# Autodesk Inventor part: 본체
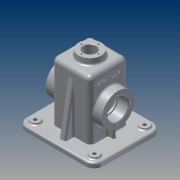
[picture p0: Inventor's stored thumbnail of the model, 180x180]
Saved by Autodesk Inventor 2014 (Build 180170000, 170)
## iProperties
Created: 2015-12
Part Number: 본체
Material: 알루미늄 6061
Document SubType Name: Modeling
Designer: Administrator
Density: 2.71 g/cm^3
Appearance: 알루미늄 - 평지
Mass: 801.49 g
Surface Area: 918.504 cm^2
Volume: 295.753 cm^3
Author: Administrator
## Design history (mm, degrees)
sketch "스케치1"
  geometry: L1 (-50, 57.5)-(50, 57.5); L2 (65, 42.5)-(65, -42.5); L3 (50, -57.5)-(-50, -57.5); L4 (-65, -42.5)-(-65, 42.5); A1 r 15 centre (-50, 42.5) between (-50, 57.5) and (-65, 42.5); A2 r 15 centre (50, 42.5) between (65, 42.5) and (50, 57.5); A3 r 15 centre (50, -42.5) between (50, -57.5) and (65, -42.5); A4 r 15 centre (-50, -42.5) between (-65, -42.5) and (-50, -57.5); 6 further points
  constraints: 8 end point, 8 point on circle, 8 tangent, 6 point on line, 4 centre point, 3 equal radius, 2 midpoint, 2 parallel, 1 horizontal, 1 horizontal alignment, 1 perpendicular, 1 vertical alignment
  dimensions: "d0" = 130 distance of point (-65, 57.5) point (65, 57.5); "d1" = 115 distance of point (65, 57.5) point (65, -57.5); "d2" = 15 radius of A1
extrude "돌출1" new body sketch "스케치1" distance "d3" = 10; taper "d4" = 0 deg
sketch "스케치2"
  geometry: L1 (-32.5, 32.5)-(32.5, 32.5); L2 (32.5, 32.5)-(32.5, -32.5); L3 (32.5, -32.5)-(-32.5, -32.5); L4 (-32.5, -32.5)-(-32.5, 32.5); 3 further points
  constraints: 8 end point, 2 midpoint, 2 parallel, 1 horizontal, 1 horizontal alignment, 1 perpendicular, 1 vertical alignment
  dimensions: "d5" = 65 distance of L1.end L2.end; "d6" = 65 distance of L1.start L1.end
extrude "돌출2" join sketch "스케치2" distance "d7" = 100; taper "d8" = 0 deg
sketch "스케치6"
  geometry: C1 r 27.5 at (-45, 32.5); 1 further point
  constraints: 1 centre point
  dimensions: "d17" = 55 distance of point (10, 32.5) C1.centre; "d18" = 55 diameter of C1
extrude "돌출3" join sketch "스케치6" distance "d19" = 15; taper "d20" = 0 deg
hole "구멍1" diameter "d23" = 30; stored, may be unused: countersink angle "d27" = 90 deg, drill point angle "d29" = 118 deg; dims "d24" = 6, "d25" = 35, "d26" = 17, "d28" = 8, "d30" = 10, "d31" = 10
sketch "스케치7"
  geometry: C1 r 17.5 at (0, 0) reference; 2 further points
  constraints: 1 horizontal alignment
  dimensions: "d32" = 21 distance of C1.centre point (-21, 0)
hole "구멍2" sketch "스케치7" at (-21, 0) diameter "d33" = 3.242; stored, may be unused: countersink angle "d37" = 90 deg, drill point angle "d39" = 118 deg; dims "d34" = 8, "d35" = 42, "d36" = 17, "d38" = 10
sketch "스케치8"
  geometry: L1 (-27.5, 27.5)-(27.5, 27.5); L2 (27.5, 27.5)-(27.5, -27.5); L3 (27.5, -27.5)-(-27.5, -27.5); L4 (-27.5, -27.5)-(-27.5, 27.5); 3 further points
  constraints: 8 end point, 2 midpoint, 2 parallel, 1 horizontal, 1 horizontal alignment, 1 perpendicular, 1 vertical alignment
  dimensions: "d43" = 55 distance of L1.start L1.end; "d44" = 55 distance of L1.end L2.end
extrude "돌출4" cut sketch "스케치8" distance "d45" = 105; taper "d46" = 0 deg
sketch "스케치9"
  geometry: C1 r 20 at (0, 0); 1 further point
  constraints: 1 centre point, 1 coincident
  dimensions: "d47" = 40 diameter of C1
extrude "돌출5" join sketch "스케치9" distance "d48" = 10; taper "d49" = -5 deg
hole "구멍3" diameter "d52" = 21; stored, may be unused: countersink angle "d56" = 90 deg, drill point angle "d58" = 118 deg; dims "d50" = 10, "d51" = 10, "d53" = 8, "d54" = 42, "d55" = 17, "d57" = 10
sketch "스케치10"
  geometry: C1 r 10.5 at (0, 0) reference; 1 further point
  constraints: 1 horizontal alignment
  dimensions: "d59" = 14.5 distance of point (14.5, 0) C1.centre
hole "구멍4" sketch "스케치10" at (14.5, 0) diameter "d60" = 2.459; stored, may be unused: countersink angle "d64" = 90 deg, drill point angle "d66" = 118 deg; dims "d61" = 7, "d62" = 42, "d63" = 17, "d65" = 9
sketch "스케치11"
  geometry: L1 (50, 57.5)-(-50, 57.5) reference; L2 (-65, 42.5)-(-65, -42.5) reference; L3 (-50, -57.5)-(50, -57.5) reference; L4 (65, -42.5)-(65, 42.5) reference; L5 (-50, 52.5)-(50, 52.5); L6 (60, 42.5)-(60, -42.5); L7 (50, -52.5)-(-50, -52.5); L8 (-60, -42.5)-(-60, 42.5); A1 r 15 centre (-50, 42.5) between (-50, 57.5) and (-65, 42.5) reference; A2 r 15 centre (-50, -42.5) between (-65, -42.5) and (-50, -57.5) reference; A3 r 15 centre (50, -42.5) between (50, -57.5) and (65, -42.5) reference; A4 r 15 centre (50, 42.5) between (65, 42.5) and (50, 57.5) reference; A5 r 10 centre (-50, 42.5) between (-50, 52.5) and (-60, 42.5); A6 r 10 centre (50, 42.5) between (60, 42.5) and (50, 52.5); A7 r 10 centre (50, -42.5) between (50, -52.5) and (60, -42.5); A8 r 10 centre (-50, -42.5) between (-60, -42.5) and (-50, -52.5); 6 further points
  constraints: 8 end point, 8 point on circle, 8 tangent, 6 point on line, 4 centre point, 3 equal radius, 2 midpoint, 2 parallel, 1 horizontal, 1 horizontal alignment, 1 perpendicular, 1 vertical alignment
  dimensions: "d70" = 120 distance of point (-60, 52.5) point (60, 52.5); "d71" = 105 distance of point (60, 52.5) point (60, -52.5); "d72" = 10 radius of A5
extrude "돌출6" cut sketch "스케치11" distance "d73" = 2; taper "d74" = 0 deg
sketch "스케치12"
  geometry: C1 r 7.5 at (-50, 42.5); C2 r 7.5 at (-50, -42.5); C3 r 7.5 at (50, -42.5); C4 r 7.5 at (50, 42.5); A1 r 15 centre (-50, 42.5) between (-50, 57.5) and (-65, 42.5) reference; A2 r 15 centre (-50, -42.5) between (-65, -42.5) and (-50, -57.5) reference; A3 r 15 centre (50, -42.5) between (50, -57.5) and (65, -42.5) reference; A4 r 15 centre (50, 42.5) between (65, 42.5) and (50, 57.5) reference; 1 further point
  constraints: 4 centre point, 4 coincident, 2 equal radius
  dimensions: "d75" = 15 diameter of C1; "d76" = 15 diameter of C2
extrude "돌출7" join sketch "스케치12" distance "d77" = 3; taper "d78" = 0 deg
sketch "스케치13"
  geometry: C1 r 7.5 at (0, 0) reference; C2 r 7.5 at (0, 85) reference; C3 r 7.5 at (-100, 85) reference; C4 r 7.5 at (-100, 0) reference; 5 further points
  constraints: 4 coincident
hole "구멍5" sketch "스케치13" at (-100, 85), (-100, 0), (0, 0), (0, 85) diameter "d79" = 6; stored, may be unused: countersink angle "d83" = 90 deg, drill point angle "d85" = 118 deg; dims "d80" = 7, "d81" = 42, "d82" = 17, "d84" = 9
sketch "스케치14"
  geometry: L1 (32.5, 82.5)-(47.5, 82.5) reference; L2 (47.5, 82.5)-(47.5, 77.621) reference; L3 (47.5, 77.621)-(37.5, 77.621) reference; L4 (37.5, 77.621)-(36.526, 76) reference; L5 (36.526, 76)-(37.5, 74.379) reference; L6 (37.5, 74.379)-(47.5, 74.379) reference; L7 (47.5, 74.379)-(47.5, 72.5) reference; L8 (47.5, 72.5)-(30.5, 72.5) reference; L9 (30.5, 72.5)-(30.5, 70) reference; L10 (30.5, 70)-(27.5, 70) reference; L11 (27.5, 70)-(27.5, 105) reference; L12 (27.5, 105)-(10.5, 105) reference; L13 (10.5, 105)-(10.5, 120) reference; L14 (10.5, 120)-(13.271, 120) reference; L15 (13.271, 120)-(13.271, 111) reference; L16 (13.271, 111)-(14.5, 110.261) reference; L17 (14.5, 110.261)-(15.73, 111) reference; L18 (15.73, 111)-(15.73, 120) reference; L19 (15.73, 120)-(19.125, 120) reference; L20 (19.125, 120)-(20, 110) reference; L21 (20, 110)-(32.5, 110) reference; L22 (32.5, 110)-(32.5, 82.5) reference; L23 (47.5, 27.5)-(32.5, 27.5) reference; L24 (32.5, 27.5)-(32.5, 10) reference; L25 (32.5, 10)-(65, 10) reference; L26 (65, 10)-(65, 2) reference; L27 (65, 2)-(60, 2) reference; L28 (60, 2)-(60, 0) reference; L29 (60, 0)-(27.5, 0) reference; L30 (27.5, 0)-(27.5, 40) reference; L31 (27.5, 40)-(30.5, 40) reference; L32 (30.5, 40)-(30.5, 37.5) reference; L33 (30.5, 37.5)-(47.5, 37.5) reference; L34 (47.5, 37.5)-(47.5, 35.621) reference; L35 (47.5, 35.621)-(37.5, 35.621) reference; L36 (37.5, 35.621)-(36.526, 34) reference; L37 (36.526, 34)-(37.5, 32.379) reference; L38 (37.5, 32.379)-(47.5, 32.379) reference; L39 (47.5, 32.379)-(47.5, 27.5) reference; L40 (-47.5, 82.5)-(-32.5, 82.5) reference; L41 (-32.5, 82.5)-(-32.5, 110) reference; L42 (-32.5, 110)-(-20, 110) reference; L43 (-20, 110)-(-19.125, 120) reference; L44 (-19.125, 120)-(-15.73, 120) reference; L45 (-15.73, 120)-(-15.73, 111) reference; L46 (-15.73, 111)-(-14.5, 110.261) reference; L47 (-14.5, 110.261)-(-13.271, 111) reference; L48 (-13.271, 111)-(-13.271, 120) reference; L49 (-13.271, 120)-(-10.5, 120) reference; L50 (-10.5, 120)-(-10.5, 105) reference; L51 (-10.5, 105)-(-27.5, 105) reference; L52 (-27.5, 105)-(-27.5, 70) reference; L53 (-27.5, 70)-(-30.5, 70) reference; L54 (-30.5, 70)-(-30.5, 72.5) reference; L55 (-30.5, 72.5)-(-47.5, 72.5) reference; L56 (-47.5, 72.5)-(-47.5, 74.379) reference; L57 (-47.5, 74.379)-(-37.5, 74.379) reference; L58 (-37.5, 74.379)-(-36.526, 76) reference; L59 (-36.526, 76)-(-37.5, 77.621) reference; L60 (-37.5, 77.621)-(-47.5, 77.621) reference; L61 (-47.5, 77.621)-(-47.5, 82.5) reference; L62 (-32.5, 27.5)-(-47.5, 27.5) reference; L63 (-47.5, 27.5)-(-47.5, 32.379) reference; L64 (-47.5, 32.379)-(-37.5, 32.379) reference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; 1 further point
  constraints: 16 end point, 4 collinear, 2 point on line, 2 vertical, 1 parallel, 1 perpendicular
  dimensions: "d87" = 15 distance between parallel lines of L72 L79; "d88" = 15 distance between parallel lines of L80 L30; "d89" = 20.28589 distance of L79.start L79.end; "d90" = 20.28651 distance of L80.start L80.end
extrude "돌출8" join sketch "스케치14" stored distance "d91" = 6; taper "d92" = 0 deg
sketch "스케치15"
  geometry: L1 (-32.5, 10)-(-32.5, 110) reference; L2 (-32.5, 110)-(-20, 110) reference; L3 (-20, 110)-(-19.125, 120) reference; L4 (-19.125, 120)-(-15.73, 120) reference; L5 (-15.73, 120)-(-15.73, 111) reference; L6 (-15.73, 111)-(-14.5, 110.261) reference; L7 (-14.5, 110.261)-(-13.271, 111) reference; L8 (-13.271, 111)-(-13.271, 120) reference; L9 (-13.271, 120)-(-10.5, 120) reference; L10 (-10.5, 120)-(-10.5, 105) reference; L11 (-10.5, 105)-(-27.5, 105) reference; L12 (-27.5, 105)-(-27.5, 0) reference; L13 (-27.5, 0)-(-52.5, 0) reference; L14 (-52.5, 0)-(-52.5, 2) reference; L15 (-52.5, 2)-(-57.5, 2) reference; L16 (-57.5, 2)-(-57.5, 10) reference; L17 (-57.5, 10)-(-32.5, 10) reference; L18 (32.5, 110)-(32.5, 10) reference; L19 (32.5, 10)-(57.5, 10) reference; L20 (57.5, 10)-(57.5, 2) reference; L21 (57.5, 2)-(52.5, 2) reference; L22 (52.5, 2)-(52.5, 0) reference; L23 (52.5, 0)-(27.5, 0) reference; L24 (27.5, 0)-(27.5, 105) reference; L25 (27.5, 105)-(10.5, 105) reference; L26 (10.5, 105)-(10.5, 120) reference; L27 (10.5, 120)-(13.271, 120) reference; L28 (13.271, 120)-(13.271, 111) reference; L29 (13.271, 111)-(14.5, 110.261) reference; L30 (14.5, 110.261)-(15.73, 111) reference; L31 (15.73, 111)-(15.73, 120) reference; L32 (15.73, 120)-(19.125, 120) reference; L33 (19.125, 120)-(20, 110) reference; L34 (20, 110)-(32.5, 110) reference; L35 (-32.5, 95.069)-(-47.5, 10); L36 (32.5, 95.069)-(47.5, 10); 1 further point
  constraints: 4 end point, 4 point on line
  dimensions: "d93" = 10 deg angle of L35 L16; "d94" = 10 deg angle of L20 L36; "d95" = 10 distance from line of L35.end L16; "d96" = 10 distance from line of L36.end L20
extrude "돌출9" join sketch "스케치15" stored distance "d97" = 10; taper "d98" = 0 deg
chamfer "모따기1" distance "d99" = 1; stored, may be unused: second distance "d100" = 2, angle "d101" = 45 deg
fillet "모깎기2" dims "d102" = 0.3
fillet "모깎기3" dims "d103" = 8
fillet "모깎기4" dims "d104" = 3
fillet "모깎기5" dims "d105" = 3
fillet "모깎기6" dims "d106" = 3
fillet "모깎기7" dims "d107" = 1
sketch "스케치17"
  geometry: L1 (0, -8)-(91, -8) reference; L2 (-18, 5.375)-(-18, 43.625) reference; 2 further points
  constraints: 1 other
  dimensions: "d112" = 32.5 distance from line of point (8, 24.5) L1; "d113" = 26 distance from line of L2 point (8, 24.5)
feature "엠보싱2" sketch "스케치17" dims "d0" = 130, "d1" = 115, "d2" = 15, "d114" = 0.5, "d115" = 0
node "솔리드1"
pattern_circular "원형 패턴1" dims angle "d41" = 360 deg
mirror "대칭1"
pattern_circular "원형 패턴2" dims angle "d68" = 360 deg
node "절단 모서리 투영1"
node "절단 모서리 투영2"
